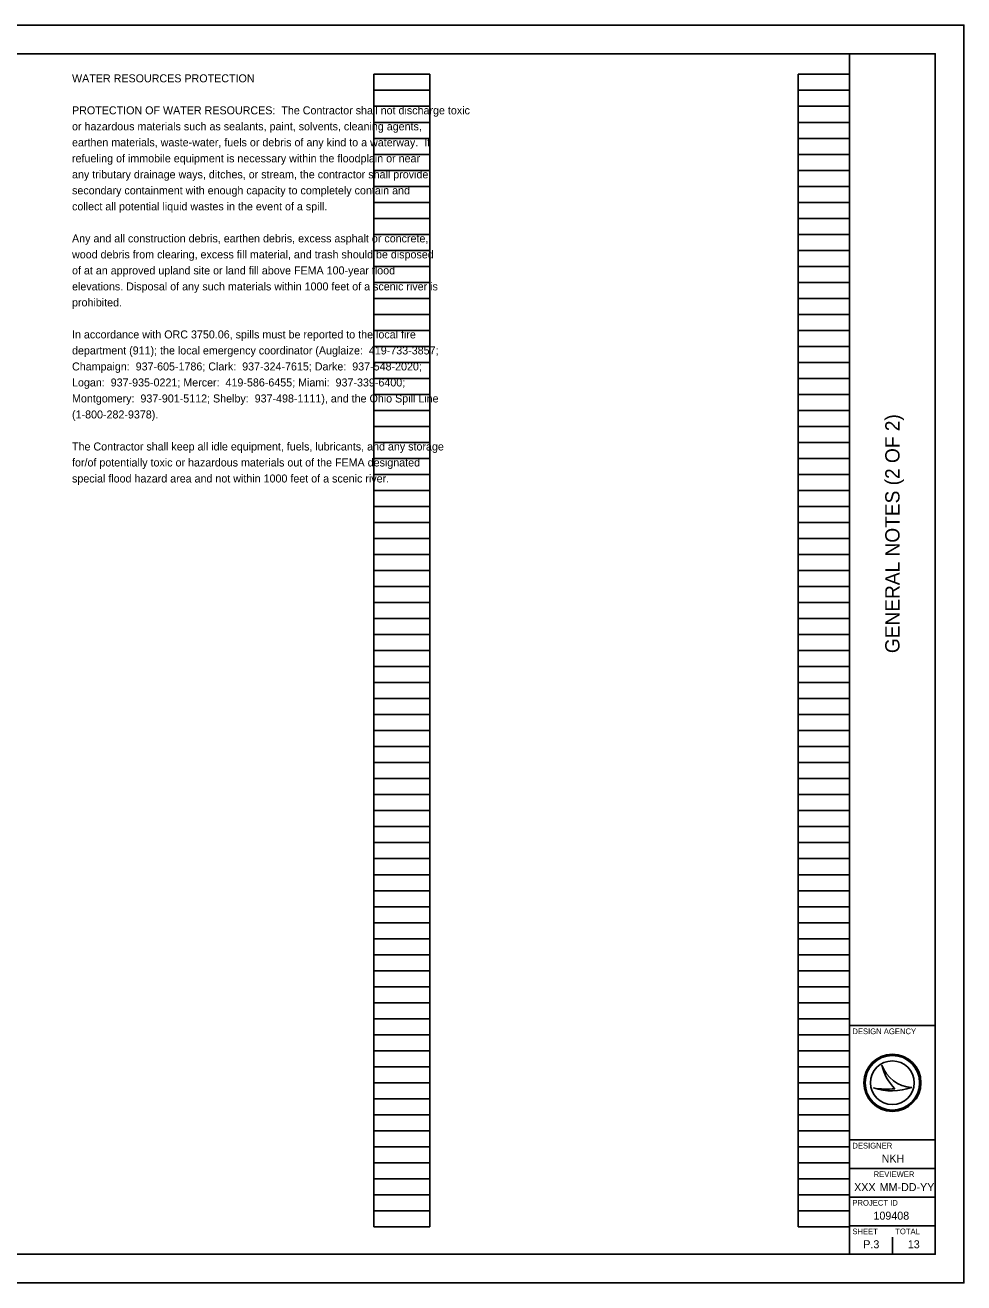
# Model space of a CAD drawing. Extents: x 0 to 41.5, y -25.5 to 22.
# Drawn here: x 17.58 to 34, y 0 to 22 of the extents above; entities that cross this region are included whole.
import ezdxf

# ---------------------------------------------------------------- set-up
doc = ezdxf.new("R2010")
doc.units = 0
for name, color, linetype in [('Default', 7, 'Continuous'), ('SH_Border', 7, 'Continuous'), ('SH_Cut_Line', 7, 'Continuous'), ('SH_Data', 7, 'Continuous'), ('SH_Text', 7, 'Continuous')]:
    doc.layers.add(name, color=color, linetype=linetype)

msp = doc.modelspace()

# ---------------------------------------------------------------- linework, layer by layer
at = {"layer": 'SH_Border'}
for p, q in [((32, 0.5), (32, 21.5)), ((32, 4.5), (33.5, 4.5)), ((32, 2.5), (33.5, 2.5)), ((32, 2), (33.5, 2)), ((32, 1.5), (33.5, 1.5)), ((32, 1), (33.5, 1))]:
    msp.add_line(p, q, dxfattribs=at)
msp.add_lwpolyline([(1.5, 21.5), (33.5, 21.5), (33.5, 0.5), (1.5, 0.5)], close=True, dxfattribs=at)
at = {"layer": 'SH_Cut_Line'}
msp.add_lwpolyline([(0, 0), (34, 0), (34, 22), (0, 22)], close=True, dxfattribs=at)
at = {"layer": 'SH_Data'}
for p, q in [((23.68, 0.98), (23.68, 21.14)), ((23.68, 21.14), (24.66, 21.14)), ((24.66, 0.98), (24.66, 21.14)), ((31.1, 0.98), (31.1, 21.14)), ((31.1, 21.14), (32, 21.14)), ((32, 0.98), (32, 21.14)), ((23.68, 20.86), (24.66, 20.86)), ((31.1, 20.86), (32, 20.86)), ((23.68, 20.58), (24.66, 20.58)), ((31.1, 20.58), (32, 20.58)), ((23.68, 20.3), (24.66, 20.3)), ((31.1, 20.3), (32, 20.3)), ((23.68, 20.02), (24.66, 20.02)), ((31.1, 20.02), (32, 20.02)), ((23.68, 19.74), (24.66, 19.74)), ((31.1, 19.74), (32, 19.74)), ((23.68, 19.46), (24.66, 19.46)), ((31.1, 19.46), (32, 19.46)), ((23.68, 19.18), (24.66, 19.18)), ((31.1, 19.18), (32, 19.18)), ((23.68, 18.9), (24.66, 18.9)), ((31.1, 18.9), (32, 18.9)), ((23.68, 18.62), (24.66, 18.62)), ((31.1, 18.62), (32, 18.62)), ((23.68, 18.34), (24.66, 18.34)), ((31.1, 18.34), (32, 18.34)), ((23.68, 18.06), (24.66, 18.06)), ((31.1, 18.06), (32, 18.06)), ((23.68, 17.78), (24.66, 17.78)), ((31.1, 17.78), (32, 17.78)), ((23.68, 17.5), (24.66, 17.5)), ((31.1, 17.5), (32, 17.5)), ((23.68, 17.22), (24.66, 17.22)), ((31.1, 17.22), (32, 17.22)), ((23.68, 16.94), (24.66, 16.94)), ((31.1, 16.94), (32, 16.94)), ((23.68, 16.66), (24.66, 16.66)), ((31.1, 16.66), (32, 16.66)), ((23.68, 16.38), (24.66, 16.38)), ((31.1, 16.38), (32, 16.38)), ((23.68, 16.1), (24.66, 16.1)), ((31.1, 16.1), (32, 16.1)), ((23.68, 15.82), (24.66, 15.82)), ((31.1, 15.82), (32, 15.82)), ((23.68, 15.54), (24.66, 15.54)), ((31.1, 15.54), (32, 15.54)), ((23.68, 15.26), (24.66, 15.26)), ((31.1, 15.26), (32, 15.26)), ((23.68, 14.98), (24.66, 14.98)), ((31.1, 14.98), (32, 14.98)), ((23.68, 14.7), (24.66, 14.7)), ((31.1, 14.7), (32, 14.7)), ((23.68, 14.42), (24.66, 14.42)), ((31.1, 14.42), (32, 14.42)), ((23.68, 14.14), (24.66, 14.14)), ((31.1, 14.14), (32, 14.14)), ((23.68, 13.86), (24.66, 13.86)), ((31.1, 13.86), (32, 13.86)), ((23.68, 13.58), (24.66, 13.58)), ((31.1, 13.58), (32, 13.58)), ((23.68, 13.3), (24.66, 13.3)), ((31.1, 13.3), (32, 13.3)), ((23.68, 13.02), (24.66, 13.02)), ((31.1, 13.02), (32, 13.02)), ((23.68, 12.74), (24.66, 12.74)), ((31.1, 12.74), (32, 12.74)), ((23.68, 12.46), (24.66, 12.46)), ((31.1, 12.46), (32, 12.46)), ((23.68, 12.18), (24.66, 12.18)), ((31.1, 12.18), (32, 12.18)), ((23.68, 11.9), (24.66, 11.9)), ((31.1, 11.9), (32, 11.9)), ((23.68, 11.62), (24.66, 11.62)), ((31.1, 11.62), (32, 11.62)), ((23.68, 11.34), (24.66, 11.34)), ((31.1, 11.34), (32, 11.34)), ((23.68, 11.06), (24.66, 11.06)), ((31.1, 11.06), (32, 11.06)), ((23.68, 10.78), (24.66, 10.78)), ((31.1, 10.78), (32, 10.78)), ((23.68, 10.5), (24.66, 10.5)), ((31.1, 10.5), (32, 10.5)), ((23.68, 10.22), (24.66, 10.22)), ((31.1, 10.22), (32, 10.22)), ((23.68, 9.94), (24.66, 9.94)), ((31.1, 9.94), (32, 9.94)), ((23.68, 9.66), (24.66, 9.66)), ((31.1, 9.66), (32, 9.66)), ((23.68, 9.38), (24.66, 9.38)), ((31.1, 9.38), (32, 9.38)), ((23.68, 9.1), (24.66, 9.1)), ((31.1, 9.1), (32, 9.1)), ((23.68, 8.82), (24.66, 8.82)), ((31.1, 8.82), (32, 8.82)), ((23.68, 8.54), (24.66, 8.54)), ((31.1, 8.54), (32, 8.54)), ((23.68, 8.26), (24.66, 8.26)), ((31.1, 8.26), (32, 8.26)), ((23.68, 7.98), (24.66, 7.98)), ((31.1, 7.98), (32, 7.98)), ((23.68, 7.7), (24.66, 7.7)), ((31.1, 7.7), (32, 7.7)), ((23.68, 7.42), (24.66, 7.42)), ((31.1, 7.42), (32, 7.42)), ((23.68, 7.14), (24.66, 7.14)), ((31.1, 7.14), (32, 7.14)), ((23.68, 6.86), (24.66, 6.86)), ((31.1, 6.86), (32, 6.86)), ((23.68, 6.58), (24.66, 6.58)), ((31.1, 6.58), (32, 6.58)), ((23.68, 6.3), (24.66, 6.3)), ((31.1, 6.3), (32, 6.3)), ((23.68, 6.02), (24.66, 6.02)), ((31.1, 6.02), (32, 6.02)), ((23.68, 5.74), (24.66, 5.74)), ((31.1, 5.74), (32, 5.74)), ((23.68, 5.46), (24.66, 5.46)), ((31.1, 5.46), (32, 5.46)), ((23.68, 5.18), (24.66, 5.18)), ((31.1, 5.18), (32, 5.18)), ((23.68, 4.9), (24.66, 4.9)), ((31.1, 4.9), (32, 4.9)), ((23.68, 4.62), (24.66, 4.62)), ((31.1, 4.62), (32, 4.62)), ((23.68, 4.34), (24.66, 4.34)), ((31.1, 4.34), (32, 4.34)), ((23.68, 4.06), (24.66, 4.06)), ((31.1, 4.06), (32, 4.06)), ((23.68, 3.78), (24.66, 3.78)), ((31.1, 3.78), (32, 3.78)), ((32.567, 3.81), (32.567, 3.81)), ((23.68, 3.5), (24.66, 3.5)), ((31.1, 3.5), (32, 3.5)), ((32.417, 3.41), (32.417, 3.41)), ((32.75, 3.5), (32.75, 3.5)), ((33.087, 3.419), (33.087, 3.419)), ((23.68, 3.22), (24.66, 3.22)), ((31.1, 3.22), (32, 3.22)), ((23.68, 2.94), (24.66, 2.94)), ((31.1, 2.94), (32, 2.94)), ((23.68, 2.66), (24.66, 2.66)), ((31.1, 2.66), (32, 2.66)), ((23.68, 2.38), (24.66, 2.38)), ((31.1, 2.38), (32, 2.38)), ((23.68, 2.1), (24.66, 2.1)), ((31.1, 2.1), (32, 2.1)), ((23.68, 1.82), (24.66, 1.82)), ((31.1, 1.82), (32, 1.82)), ((23.68, 1.54), (24.66, 1.54)), ((31.1, 1.54), (32, 1.54)), ((23.68, 1.26), (24.66, 1.26)), ((31.1, 1.26), (32, 1.26)), ((23.68, 0.98), (24.66, 0.98)), ((31.1, 0.98), (32, 0.98)), ((32.375, 0.675), (32.375, 0.675)), ((32.75, 0.5), (32.75, 0.8))]:
    msp.add_line(p, q, dxfattribs=at)
for radius in [0.5, 0.477, 0.477, 0.382]:
    msp.add_circle((32.75, 3.5), radius, dxfattribs=at)
for centre, radius, start, end in [((33.116, 3.998), 0.58, 198.9257, 198.9319), ((33.347, 3.97), 0.796, 191.6379, 191.6421), ((33.116, 3.998), 0.58, 198.9319, 267.1657), ((33.347, 3.97), 0.796, 191.6421, 226.0947), ((32.739, 4.37), 1.013, 251.4576, 290.0832), ((32.648, 4.654), 1.266, 259.4964, 259.4995), ((32.739, 4.37), 1.013, 251.4527, 251.4576), ((32.648, 4.654), 1.266, 259.4995, 276.6672)]:
    msp.add_arc(centre, radius, start, end, dxfattribs=at)

# ---------------------------------------------------------------- texts
at = {"layer": 'Default'}
msp.add_text('WATER RESOURCES PROTECTION', height=0.14, dxfattribs=at).set_placement((18.4, 21))
at = {"layer": 'SH_Data'}
msp.add_text('GENERAL NOTES (2 OF 2)', height=0.25, rotation=90, dxfattribs=at).set_placement((32.875, 11.015))
for s, height, p in [('DESIGN AGENCY', 0.1, (32.05, 4.35)), ('DESIGNER', 0.1, (32.05, 2.35)), ('NKH', 0.14, (32.562, 2.105)), ('REVIEWER', 0.1, (32.422, 1.85)), ('XXX', 0.14, (32.081, 1.605)), ('MM-DD-YY', 0.14, (32.527, 1.605)), ('PROJECT ID', 0.1, (32.05, 1.35)), ('109408', 0.14, (32.419, 1.105)), ('SHEET', 0.1, (32.05, 0.85)), ('TOTAL', 0.1, (32.8, 0.85)), ('P.3', 0.14, (32.241, 0.605)), ('13', 0.14, (33.02, 0.605))]:
    msp.add_text(s, height=height, dxfattribs=at).set_placement(p)
at = {"layer": 'SH_Text'}
for s, p in [('PROTECTION OF WATER RESOURCES:  The Contractor shall not discharge toxic ', (18.4, 20.44)), ('or hazardous materials such as sealants, paint, solvents, cleaning agents, ', (18.4, 20.16)), ('earthen materials, waste-water, fuels or debris of any kind to a waterway.  If ', (18.4, 19.88)), ('refueling of immobile equipment is necessary within the floodplain or near ', (18.4, 19.6)), ('any tributary drainage ways, ditches, or stream, the contractor shall provide ', (18.4, 19.32)), ('secondary containment with enough capacity to completely contain and ', (18.4, 19.04)), ('collect all potential liquid wastes in the event of a spill.', (18.4, 18.76)), ('Any and all construction debris, earthen debris, excess asphalt or concrete, ', (18.4, 18.2)), ('wood debris from clearing, excess fill material, and trash should be disposed ', (18.4, 17.92)), ('of at an approved upland site or land fill above FEMA 100-year flood ', (18.4, 17.64)), ('elevations. Disposal of any such materials within 1000 feet of a scenic river is ', (18.4, 17.36)), ('prohibited.', (18.4, 17.08)), ('In accordance with ORC 3750.06, spills must be reported to the local fire ', (18.4, 16.52)), ('department (911); the local emergency coordinator (Auglaize:  419-733-3857; ', (18.4, 16.24)), ('Champaign:  937-605-1786; Clark:  937-324-7615; Darke:  937-548-2020; ', (18.4, 15.96)), ('Logan:  937-935-0221; Mercer:  419-586-6455; Miami:  937-339-6400; ', (18.4, 15.68)), ('Montgomery:  937-901-5112; Shelby:  937-498-1111), and the Ohio Spill Line ', (18.4, 15.4)), ('(1-800-282-9378).', (18.4, 15.12)), ('The Contractor shall keep all idle equipment, fuels, lubricants, and any storage ', (18.4, 14.56)), ('for/of potentially toxic or hazardous materials out of the FEMA designated ', (18.4, 14.28)), ('special flood hazard area and not within 1000 feet of a scenic river.', (18.4, 14))]:
    msp.add_text(s, height=0.14, dxfattribs=at).set_placement(p)

doc.saveas('drawing.dxf')
